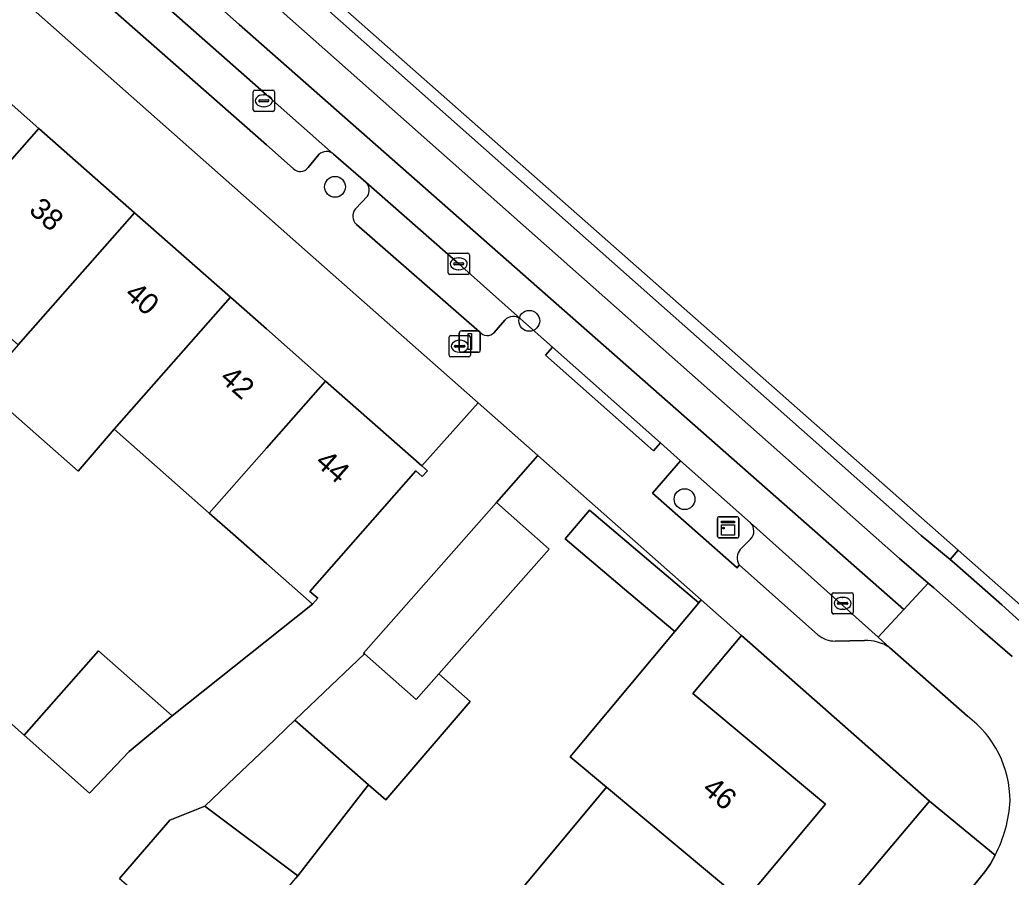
# Model space of a CAD drawing. Extents: x 162523 to 163266, y 381230 to 382050.
# Drawn here: x 162988.4 to 163035.02, y 381826.43 to 381866.76 of the extents above; entities that cross this region are included whole.
import ezdxf

# ---------------------------------------------------------------- set-up
doc = ezdxf.new("R2010")
doc.units = 0
for name, color, linetype in [('IMGEO_Boom', 7, 'Continuous'), ('IMGEO_Brandkraan', 7, 'Continuous'), ('IMGEO_Erf', 7, 'Continuous'), ('IMGEO_Groenvoorziening', 7, 'Continuous'), ('IMGEO_Kast', 7, 'Continuous'), ('IMGEO_Kolk', 7, 'Continuous'), ('IMGEO_Lichtmast', 7, 'Continuous'), ('IMGEO_Muur', 7, 'Continuous'), ('IMGEO_Pand', 7, 'Continuous'), ('IMGEO_Pand_nummerreeks', 7, 'Continuous'), ('IMGEO_Parkeervlak_open', 7, 'Continuous'), ('IMGEO_Rijbaan_lokaal_gesloten', 7, 'Continuous'), ('IMGEO_Rijbaan_lokaal_open', 7, 'Continuous'), ('IMGEO_Verkeerseiland_gesloten', 7, 'Continuous'), ('IMGEO_Voetpad_open', 7, 'Continuous')]:
    doc.layers.add(name, color=color, linetype=linetype)

msp = doc.modelspace()

# ---------------------------------------------------------------- linework, layer by layer
at = {"layer": 'IMGEO_Boom'}
for centre in [(163003.224, 381858.903), (163012.36, 381852.6), (163019.663, 381844.21)]:
    msp.add_circle(centre, 0.489, dxfattribs=at)
at = {"layer": 'IMGEO_Brandkraan'}
for p, q in [((163008.59, 381850.977), (163008.59, 381851.829)), ((163008.665, 381851.903), (163009.517, 381851.903)), ((163009.078, 381851.683), (163009.103, 381851.683)), ((163009.591, 381851.829), (163009.591, 381850.977)), ((163008.849, 381851.397), (163008.849, 381851.409)), ((163009.287, 381851.36), (163008.889, 381851.36)), ((163008.892, 381851.446), (163009.29, 381851.446)), ((163009.101, 381851.123), (163009.076, 381851.123)), ((163009.333, 381851.409), (163009.333, 381851.397)), ((163009.517, 381850.903), (163008.665, 381850.903))]:
    msp.add_line(p, q, dxfattribs=at)
for points in [[(163008.59, 381850.977), (163008.59, 381851.829)], [(163008.665, 381851.903), (163009.517, 381851.903)], [(163009.591, 381851.829), (163009.591, 381850.977)], [(163009.517, 381850.903), (163008.665, 381850.903)]]:
    msp.add_lwpolyline(points, dxfattribs=at)
for centre, radius, start, end in [((163008.667, 381851.827), 0.0765, 91.552, 178.448), ((163008.667, 381851.827), 0.0765, 91.552, 178.448), ((163009.515, 381851.827), 0.0765, 1.552, 88.448), ((163009.515, 381851.827), 0.0765, 1.552, 88.448), ((163008.889, 381851.406), 0.0403, 85.8775, 175.7526), ((163008.886, 381851.396), 0.0366, 178.938, 274.7102), ((163009.29, 381851.403), 0.043, 264.8664, 352.4533), ((163009.294, 381851.408), 0.0386, 1.7309, 96.639), ((163008.667, 381850.979), 0.0765, 181.552, 268.448), ((163008.667, 381850.979), 0.0765, 181.552, 268.448), ((163009.515, 381850.979), 0.0765, 271.552, 358.448), ((163009.515, 381850.979), 0.0765, 271.552, 358.448)]:
    msp.add_arc(centre, radius, start, end, dxfattribs=at)
for centre, major_axis, ratio, start_param, end_param in [((163009.077, 381851.403), (-0.387, 0.002), 0.722429, 4.712389, 7.853982), ((163009.102, 381851.403), (-0.39, 0.002), 0.717154, 1.570796, 4.712389)]:
    msp.add_ellipse(centre, major_axis=major_axis, ratio=ratio, start_param=start_param, end_param=end_param, dxfattribs=at)
at = {"layer": 'IMGEO_Erf'}
msp.add_lwpolyline([(162969.525, 381884.497), (162966.83, 381881.451), (162971.462, 381877.369), (162975.895, 381873.462), (162980.362, 381869.524), (162984.945, 381865.485), (162989.296, 381861.65), (162993.798, 381857.682), (162998.309, 381853.707), (163000, 381852.216), (163002.779, 381849.766), (163007.303, 381845.78), (163009.953, 381848.745), (163001.931, 381855.827), (163000, 381857.535)], close=True, dxfattribs=at)
for points in [[(162986.402, 381835.061), (162988.598, 381833.103), (162992.096, 381837.075), (162995.563, 381834.021), (163002.168, 381839.272), (163001.86, 381839.544), (163000, 381841.183), (162998.417, 381842.578), (162997.307, 381843.556), (162992.834, 381847.497), (162991.15, 381845.534), (162986.609, 381849.516)], [(163012.008, 381825.886), (163015.993, 381830.656), (163014.279, 381832.088), (163014.913, 381832.847), (163019.202, 381837.982), (163017.04, 381839.811), (163014.052, 381842.339), (163015.193, 381843.688), (163018.181, 381841.16), (163020.334, 381839.338), (163020.45, 381839.477), (163015.189, 381844.122), (163012.767, 381846.26), (163010.813, 381844.047), (163013.288, 381841.865), (163008.108, 381835.988), (163009.581, 381834.699), (163005.62, 381830.065), (163004.802, 381830.78), (163004.732, 381830.69), (163004.629, 381830.557), (163004.565, 381830.475), (163004.343, 381830.188), (163001.473, 381826.491), (163001.369, 381826.369)], [(163031.179, 381830.005), (163022.344, 381837.805), (163020.055, 381835.066), (163026.287, 381829.86), (163022.448, 381825.264), (163021.846, 381824.543), (163022.152, 381824.287), (163020.685, 381822.532), (163020.315, 381822.841), (163018.399, 381820.548), (163014.615, 381816.018), (163010.707, 381811.338), (163006.935, 381806.824), (163003.119, 381802.254), (163000, 381798.521), (162999.285, 381797.665), (162995.128, 381792.689), (162992.81, 381794.625), (162988.817, 381789.845), (162991.441, 381785.976)], [(162997.617, 381790.181), (162997.806, 381790.405), (163031.179, 381830.005)]]:
    msp.add_lwpolyline(points, dxfattribs=at)
at = {"layer": 'IMGEO_Groenvoorziening'}
for points in [[(163019.464, 381846.01), (163018.152, 381844.491), (163022.134, 381840.979), (163022.229, 381841.123)], [(163022.766, 381843.093), (163019.464, 381846.01)], [(163022.282, 381841.85), (163022.767, 381842.333)]]:
    msp.add_lwpolyline(points, dxfattribs=at)
for centre, radius, start, end in [((163022.38, 381842.712), 0.542, 315.5657, 44.5851), ((163022.775, 381841.449), 0.636, 140.8591, 210.8017)]:
    msp.add_arc(centre, radius, start, end, dxfattribs=at)
at = {"layer": 'IMGEO_Kast'}
for p, q in [((163021.212, 381842.46), (163021.212, 381843.301)), ((163021.212, 381843.301), (163021.212, 381842.46)), ((163021.287, 381843.385), (163022.128, 381843.385)), ((163022.128, 381843.385), (163021.287, 381843.385)), ((163022.212, 381843.31), (163022.212, 381842.469)), ((163022.212, 381842.469), (163022.212, 381843.31)), ((163022.137, 381842.385), (163021.296, 381842.385)), ((163021.296, 381842.385), (163022.137, 381842.385))]:
    msp.add_line(p, q, dxfattribs=at)
for points in [[(163021.407, 381843.175), (163022.007, 381843.175), (163022.007, 381843.09), (163021.407, 381843.09), (163021.407, 381843.175)], [(163021.407, 381843), (163022.007, 381843), (163022.007, 381842.511), (163021.407, 381842.511), (163021.407, 381843)]]:
    msp.add_lwpolyline(points, dxfattribs=at)
msp.add_circle((163021.491, 381842.849), 0.0377, dxfattribs=at)
for centre, start, end in [((163021.29, 381843.307), 92.4484, 184.2845), ((163021.29, 381843.307), 92.4484, 184.2845), ((163022.134, 381843.307), 2.4484, 94.2845), ((163022.134, 381843.307), 2.4484, 94.2845), ((163021.29, 381842.463), 182.4484, 274.2845), ((163021.29, 381842.463), 182.4484, 274.2845), ((163022.134, 381842.463), 272.4484, 4.2845), ((163022.134, 381842.463), 272.4484, 4.2845)]:
    msp.add_arc(centre, 0.0779, start, end, dxfattribs=at)
at = {"layer": 'IMGEO_Kolk'}
for p, q in [((162999.376, 381862.523), (162999.376, 381863.375)), ((162999.451, 381863.449), (163000.303, 381863.449)), ((162999.864, 381863.229), (162999.889, 381863.229)), ((163000.377, 381863.375), (163000.377, 381862.523)), ((162999.635, 381862.943), (162999.635, 381862.955)), ((163000.073, 381862.906), (162999.675, 381862.906)), ((162999.678, 381862.992), (163000.076, 381862.992)), ((163000.119, 381862.955), (163000.119, 381862.943)), ((163000.303, 381862.449), (162999.451, 381862.449)), ((162999.887, 381862.669), (162999.862, 381862.669)), ((163008.617, 381855.782), (163009.469, 381855.782)), ((163008.542, 381854.856), (163008.542, 381855.708)), ((163008.801, 381855.276), (163008.801, 381855.288)), ((163008.844, 381855.325), (163009.242, 381855.325)), ((163009.03, 381855.562), (163009.055, 381855.562)), ((163009.285, 381855.288), (163009.285, 381855.276)), ((163009.543, 381855.708), (163009.543, 381854.856)), ((163009.239, 381855.239), (163008.841, 381855.239)), ((163009.053, 381855.002), (163009.028, 381855.002)), ((163009.469, 381854.782), (163008.617, 381854.782)), ((163026.594, 381838.883), (163026.594, 381839.735)), ((163026.669, 381839.809), (163027.521, 381839.809)), ((163027.082, 381839.589), (163027.107, 381839.589)), ((163027.595, 381839.735), (163027.595, 381838.883)), ((163026.853, 381839.303), (163026.853, 381839.315)), ((163027.291, 381839.266), (163026.893, 381839.266)), ((163026.896, 381839.352), (163027.294, 381839.352)), ((163027.105, 381839.029), (163027.08, 381839.029)), ((163027.337, 381839.315), (163027.337, 381839.303)), ((163027.521, 381838.809), (163026.669, 381838.809))]:
    msp.add_line(p, q, dxfattribs=at)
for points in [[(162999.376, 381862.523), (162999.376, 381863.375)], [(162999.451, 381863.449), (163000.303, 381863.449)], [(163000.377, 381863.375), (163000.377, 381862.523)], [(163000.303, 381862.449), (162999.451, 381862.449)], [(163008.617, 381855.782), (163009.469, 381855.782)], [(163008.542, 381854.856), (163008.542, 381855.708)], [(163009.543, 381855.708), (163009.543, 381854.856)], [(163009.469, 381854.782), (163008.617, 381854.782)], [(163026.594, 381838.883), (163026.594, 381839.735)], [(163026.669, 381839.809), (163027.521, 381839.809)], [(163027.595, 381839.735), (163027.595, 381838.883)], [(163027.521, 381838.809), (163026.669, 381838.809)]]:
    msp.add_lwpolyline(points, dxfattribs=at)
for centre, radius, start, end in [((162999.453, 381863.373), 0.0765, 91.552, 178.448), ((162999.453, 381863.373), 0.0765, 91.552, 178.448), ((163000.301, 381863.373), 0.0765, 1.552, 88.448), ((163000.301, 381863.373), 0.0765, 1.552, 88.448), ((162999.675, 381862.952), 0.0403, 85.8775, 175.7526), ((162999.672, 381862.942), 0.0366, 178.938, 274.7102), ((163000.076, 381862.949), 0.043, 264.8664, 352.4533), ((163000.08, 381862.954), 0.0386, 1.7309, 96.639), ((162999.453, 381862.525), 0.0765, 181.552, 268.448), ((162999.453, 381862.525), 0.0765, 181.552, 268.448), ((163000.301, 381862.525), 0.0765, 271.552, 358.448), ((163000.301, 381862.525), 0.0765, 271.552, 358.448), ((163008.619, 381855.706), 0.0765, 91.552, 178.448), ((163008.619, 381855.706), 0.0765, 91.552, 178.448), ((163009.467, 381855.706), 0.0765, 1.552, 88.448), ((163009.467, 381855.706), 0.0765, 1.552, 88.448), ((163008.841, 381855.285), 0.0403, 85.8775, 175.7526), ((163008.838, 381855.275), 0.0366, 178.938, 274.7102), ((163009.242, 381855.282), 0.043, 264.8664, 352.4533), ((163009.246, 381855.287), 0.0386, 1.7309, 96.639), ((163008.619, 381854.858), 0.0765, 181.552, 268.448), ((163008.619, 381854.858), 0.0765, 181.552, 268.448), ((163009.467, 381854.858), 0.0765, 271.552, 358.448), ((163009.467, 381854.858), 0.0765, 271.552, 358.448), ((163026.671, 381839.733), 0.0765, 91.552, 178.448), ((163026.671, 381839.733), 0.0765, 91.552, 178.448), ((163027.519, 381839.733), 0.0765, 1.552, 88.448), ((163027.519, 381839.733), 0.0765, 1.552, 88.448), ((163026.893, 381839.312), 0.0403, 85.8775, 175.7526), ((163026.89, 381839.302), 0.0366, 178.938, 274.7102), ((163027.294, 381839.309), 0.043, 264.8664, 352.4533), ((163027.298, 381839.314), 0.0386, 1.7309, 96.639), ((163026.671, 381838.885), 0.0765, 181.552, 268.448), ((163026.671, 381838.885), 0.0765, 181.552, 268.448), ((163027.519, 381838.885), 0.0765, 271.552, 358.448), ((163027.519, 381838.885), 0.0765, 271.552, 358.448)]:
    msp.add_arc(centre, radius, start, end, dxfattribs=at)
for centre, major_axis, ratio, start_param, end_param in [((162999.863, 381862.949), (-0.387, 0.002), 0.722429, 4.712389, 7.853982), ((162999.888, 381862.949), (-0.39, 0.002), 0.717154, 1.570796, 4.712389), ((163009.029, 381855.282), (-0.387, 0.002), 0.722429, 4.712389, 7.853982), ((163009.054, 381855.282), (-0.39, 0.002), 0.717154, 1.570796, 4.712389), ((163027.081, 381839.309), (-0.387, 0.002), 0.722429, 4.712389, 7.853982), ((163027.106, 381839.309), (-0.39, 0.002), 0.717154, 1.570796, 4.712389)]:
    msp.add_ellipse(centre, major_axis=major_axis, ratio=ratio, start_param=start_param, end_param=end_param, dxfattribs=at)
at = {"layer": 'IMGEO_Lichtmast'}
for p, q in [((163009.066, 381851.225), (163009.066, 381852.025)), ((163009.066, 381852.025), (163009.066, 381851.225)), ((163009.166, 381852.125), (163009.956, 381852.125)), ((163009.956, 381852.125), (163009.166, 381852.125)), ((163010.056, 381852.025), (163010.056, 381851.225)), ((163010.056, 381851.225), (163010.056, 381852.025)), ((163009.956, 381851.125), (163009.166, 381851.125)), ((163009.166, 381851.125), (163009.956, 381851.125))]:
    msp.add_line(p, q, dxfattribs=at)
msp.add_lwpolyline([(163009.486, 381852), (163009.636, 381852), (163009.636, 381851.25), (163009.486, 381851.25), (163009.486, 381852)], dxfattribs=at)
for centre, start, end in [((163009.166, 381852.025), 90, 180), ((163009.166, 381852.025), 90, 180), ((163009.956, 381852.025), 0, 90), ((163009.956, 381852.025), 360, 90), ((163009.166, 381851.225), 180, 270), ((163009.166, 381851.225), 180, 270), ((163009.956, 381851.225), 270, 0), ((163009.956, 381851.225), 270, 0)]:
    msp.add_arc(centre, 0.1, start, end, dxfattribs=at)
at = {"layer": 'IMGEO_Muur'}
msp.add_lwpolyline([(163002.168, 381839.272), (162995.563, 381834.021)], dxfattribs=at)
at = {"layer": 'IMGEO_Pand'}
for points in [[(162979.47, 381859.272), (162983.821, 381855.439), (162989.296, 381861.65), (162984.945, 381865.485)], [(162988.324, 381851.471), (162993.798, 381857.682), (162989.296, 381861.65), (162983.821, 381855.439)], [(162992.834, 381847.497), (162998.309, 381853.707), (162993.798, 381857.682), (162988.324, 381851.471), (162986.609, 381849.516), (162991.15, 381845.534)], [(162992.834, 381847.497), (162997.307, 381843.556), (163000, 381846.613), (163002.779, 381849.766), (163000, 381852.216), (162998.309, 381853.707)], [(162997.307, 381843.556), (162998.417, 381842.578), (163000, 381841.183), (163001.86, 381839.544), (163002.168, 381839.272), (163002.409, 381839.546), (163002.037, 381839.874), (163007.03, 381845.537), (163007.329, 381845.273), (163007.569, 381845.545), (163007.303, 381845.78), (163002.779, 381849.766), (163000, 381846.613)], [(163013.288, 381841.865), (163010.813, 381844.047), (163004.569, 381836.966), (163004.609, 381836.93), (163007.045, 381834.783), (163008.108, 381835.988)], [(163015.193, 381843.688), (163014.052, 381842.339), (163017.04, 381839.811), (163019.202, 381837.982), (163020.334, 381839.338), (163018.181, 381841.16)], [(163020.055, 381835.066), (163022.344, 381837.805), (163020.45, 381839.477), (163020.334, 381839.338), (163019.202, 381837.982), (163014.913, 381832.847), (163014.279, 381832.088), (163015.993, 381830.656), (163022.448, 381825.264), (163026.287, 381829.86)], [(162995.563, 381834.021), (162992.096, 381837.075), (162988.598, 381833.103), (162991.685, 381830.384), (162993.54, 381832.337)], [(163008.108, 381835.988), (163007.045, 381834.783), (163004.609, 381836.93), (163003.972, 381836.322), (163003.049, 381835.442), (163001.339, 381833.81), (163003.018, 381832.341), (163004.802, 381830.78), (163005.62, 381830.065), (163009.581, 381834.699)], [(163001.339, 381833.81), (163000, 381832.532), (162998.532, 381831.131), (162997.107, 381829.771), (163001.473, 381826.491), (163004.343, 381830.188), (163004.565, 381830.475), (163004.629, 381830.557), (163004.732, 381830.69), (163004.802, 381830.78), (163003.018, 381832.341)], [(163015.993, 381830.656), (163012.008, 381825.886), (163018.399, 381820.548), (163020.315, 381822.841), (163020.685, 381822.532), (163022.152, 381824.287), (163021.846, 381824.543), (163022.448, 381825.264)], [(162997.107, 381829.771), (162995.45, 381829.117), (162993.09, 381826.366), (162994.289, 381825.331), (162994.834, 381824.86), (162997.663, 381822.417), (162997.88, 381822.23), (163001.082, 381826.028), (163001.369, 381826.369), (163001.473, 381826.491)]]:
    msp.add_lwpolyline(points, close=True, dxfattribs=at)
at = {"layer": 'IMGEO_Parkeervlak_open'}
for points in [[(163003.157, 381860.44), (163000, 381863.226), (162991.553, 381870.7)], [(162991.105, 381868.722), (163000, 381860.883), (163001.263, 381859.77)], [(163001.956, 381859.806), (163002.457, 381860.419)], [(163011.941, 381852.697), (163009.04, 381855.284), (163004.675, 381859.124)], [(163004.752, 381858.461), (163004.192, 381857.868)], [(163004.231, 381857.137), (163010.025, 381852.084)], [(163010.703, 381852.049), (163011.212, 381852.638)], [(163029.301, 381837.237), (163028.767, 381837.716), (163022.766, 381843.093)], [(163022.767, 381842.333), (163022.282, 381841.85)], [(163022.229, 381841.123), (163025.932, 381837.829)], [(163026.742, 381837.537), (163028.124, 381837.564)]]:
    msp.add_lwpolyline(points, dxfattribs=at)
for centre, radius, start, end in [((163002.819, 381860.041), 0.523, 49.6765, 133.7602), ((163001.595, 381860.067), 0.445, 221.7795, 324.168), ((163004.286, 381858.743), 0.544, 328.8126, 44.4366), ((163004.58, 381857.522), 0.52, 138.2869, 227.821), ((163011.612, 381852.228), 0.573, 54.9545, 134.2995), ((163010.379, 381852.35), 0.442, 216.9304, 317.1593), ((163022.38, 381842.712), 0.542, 315.5657, 44.5851), ((163022.775, 381841.449), 0.636, 140.8591, 210.8017), ((163026.723, 381838.753), 1.216, 229.4385, 270.9136), ((163028.181, 381835.488), 2.077, 57.3733, 91.5735)]:
    msp.add_arc(centre, radius, start, end, dxfattribs=at)
at = {"layer": 'IMGEO_Rijbaan_lokaal_gesloten'}
for points in [[(163032.53, 381841.809), (162977.77, 381890.123), (162960.892, 381905.077), (162960.555, 381904.688), (162964.495, 381901.237), (163030.789, 381842.506), (163032.151, 381841.367)], [(162959.588, 381903.618), (162958.336, 381902.201), (162984.668, 381879.012), (162998.723, 381866.534), (163029.975, 381839.023), (163031.123, 381840.264), (163029.773, 381841.426), (162963.496, 381900.145)], [(162967.56, 381891.81), (162971.423, 381888.432), (162973.433, 381886.74), (162980.579, 381880.401), (162982.129, 381879.043), (162988.186, 381873.694), (162989.627, 381872.433), (162991.553, 381870.7), (163000, 381863.226), (163003.157, 381860.44), (163004.675, 381859.124), (163009.04, 381855.284), (163011.941, 381852.697), (163013.455, 381851.365), (163018.527, 381846.856), (163019.464, 381846.01), (163022.766, 381843.093), (163028.767, 381837.716), (163029.975, 381839.023), (162998.723, 381866.534), (162984.668, 381879.012), (162958.336, 381902.201), (162957.238, 381900.957)]]:
    msp.add_lwpolyline(points, close=True, dxfattribs=at)
at = {"layer": 'IMGEO_Rijbaan_lokaal_open'}
for points in [[(162993.09, 381826.366), (162995.45, 381829.117), (162997.107, 381829.771), (162998.532, 381831.131), (163000, 381832.532), (163001.339, 381833.81), (163003.049, 381835.442), (163003.972, 381836.322), (163004.609, 381836.93), (163004.569, 381836.966), (163010.813, 381844.047), (163012.767, 381846.26), (163009.953, 381848.745), (163007.303, 381845.78), (163007.569, 381845.545), (163007.329, 381845.273), (163007.03, 381845.537), (163002.037, 381839.874), (163002.409, 381839.546), (163002.168, 381839.272), (162995.563, 381834.021), (162993.54, 381832.337), (162991.685, 381830.384), (162988.598, 381833.103), (162986.402, 381835.061)], [(163053.906, 381823.577), (163040.664, 381834.632), (163032.53, 381841.809), (163032.151, 381841.367), (163032.351, 381841.2), (163034.587, 381839.245), (163037.615, 381836.491)], [(163035.073, 381836.804), (163033.583, 381838.09), (163031.383, 381840.04), (163031.123, 381840.264), (163029.975, 381839.023), (163028.767, 381837.716), (163029.301, 381837.237), (163032.966, 381834.001)], [(163034.271, 381827.468), (163034.045, 381827.064), (163033.791, 381826.677), (163031.945, 381824.423), (163036.072, 381820.914), (163036.33, 381821.22), (163037.101, 381822.132)]]:
    msp.add_lwpolyline(points, dxfattribs=at)
for centre, radius, start, end in [((163029.978, 381829.999), 4.994, 0.1903, 53.25), ((163028.493, 381830.428), 6.493, 332.8749, 356.3601)]:
    msp.add_arc(centre, radius, start, end, dxfattribs=at)
at = {"layer": 'IMGEO_Verkeerseiland_gesloten'}
for points in [[(162956.725, 381906.162), (162959.588, 381903.618), (162963.496, 381900.145), (163029.773, 381841.426), (163031.123, 381840.264), (163031.383, 381840.04), (163033.583, 381838.09), (163035.073, 381836.804)], [(163037.615, 381836.491), (163034.587, 381839.245), (163032.351, 381841.2), (163032.151, 381841.367), (163030.789, 381842.506), (162964.495, 381901.237)]]:
    msp.add_lwpolyline(points, dxfattribs=at)
at = {"layer": 'IMGEO_Voetpad_open'}
for points in [[(162951.769, 381900.206), (162968.368, 381885.521), (162969.525, 381884.497), (163000, 381857.535), (163001.931, 381855.827), (163009.953, 381848.745), (163012.767, 381846.26), (163015.189, 381844.122), (163020.45, 381839.477), (163022.344, 381837.805), (163031.179, 381830.005), (163034.271, 381827.468)], [(163001.263, 381859.77), (163000, 381860.883), (162991.105, 381868.722)], [(163002.457, 381860.419), (163001.956, 381859.806)], [(163004.675, 381859.124), (163003.157, 381860.44)], [(163004.192, 381857.868), (163004.752, 381858.461)], [(163010.025, 381852.084), (163004.231, 381857.137)], [(163011.212, 381852.638), (163010.703, 381852.049)], [(163025.932, 381837.829), (163022.229, 381841.123), (163022.134, 381840.979), (163018.152, 381844.491), (163019.464, 381846.01), (163018.527, 381846.856), (163018.195, 381846.483), (163013.123, 381850.992), (163013.455, 381851.365), (163011.941, 381852.697)], [(163028.124, 381837.564), (163026.742, 381837.537)], [(163032.966, 381834.001), (163029.301, 381837.237)], [(163031.165, 381823.49), (163031.945, 381824.423), (163033.791, 381826.677), (163034.045, 381827.064), (163034.271, 381827.468), (163031.179, 381830.005), (162997.806, 381790.405), (162997.617, 381790.181)]]:
    msp.add_lwpolyline(points, dxfattribs=at)
msp.add_lwpolyline([(163018.527, 381846.856), (163013.455, 381851.365), (163013.123, 381850.992), (163018.195, 381846.483)], close=True, dxfattribs=at)
for centre, radius, start, end in [((163002.819, 381860.041), 0.523, 49.6765, 133.7602), ((163001.595, 381860.067), 0.445, 221.7795, 324.168), ((163004.286, 381858.743), 0.544, 328.8126, 44.4366), ((163004.58, 381857.522), 0.52, 138.2869, 227.821), ((163011.612, 381852.228), 0.573, 54.9545, 134.2995), ((163010.379, 381852.35), 0.442, 216.9304, 317.1593), ((163026.723, 381838.753), 1.216, 229.4385, 270.9136), ((163028.181, 381835.488), 2.077, 57.3733, 91.5735), ((163029.978, 381829.999), 4.994, 0.1903, 53.25), ((163028.493, 381830.428), 6.493, 332.8749, 356.3601)]:
    msp.add_arc(centre, radius, start, end, dxfattribs=at)

# ---------------------------------------------------------------- texts
at = {"layer": 'IMGEO_Pand_nummerreeks'}
for s, rotation, p in [('38', 318.6077, (162988.777, 381857.735)), ('40', 318.6077, (162993.274, 381853.772)), ('42', 318.6077, (162997.752, 381849.824)), ('44', 318.6084, (163002.236, 381845.873)), ('46', 320.1279, (163020.434, 381830.475))]:
    msp.add_text(s, height=1, rotation=rotation, dxfattribs=at).set_placement(p)

doc.saveas('drawing.dxf')
